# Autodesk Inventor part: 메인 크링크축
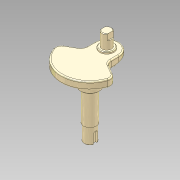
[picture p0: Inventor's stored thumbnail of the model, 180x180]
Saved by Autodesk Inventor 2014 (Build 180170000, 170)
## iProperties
Manager: KYOUNG IL JANG
Company: 한국ATC센터
Created: 2012-10
Part Number: 메인 크링크축
Document SubType Name: Modeling
Density: 1 g/cm^3
Checked By: KYOUNG IL JANG
Vendor: CBT Solutions
Designer: KYOUNG IL JANG
Material: 일반
Appearance: _시험_금속-티타늄(광택)
크링크폭: 19.000 mm
크랭크길이: 18.000 mm
크랭키위치: 65.000 mm
무게추: 90.000 mm
크랭크각도높이: 21.000 mm
크링크각도: -15.00 deg
Author: KYOUNG IL JANG
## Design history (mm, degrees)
sketch "스케치1"
  geometry: L1 (-19, 109.368)-(-19, 91.368); L2 (-19, 91.368)-(-44.545, 76.619); L3 (19, 109.368)-(19, 91.368); L4 (19, 91.368)-(44.545, 76.619); C1 r 32.5 at (0, 83) reference; C2 r 10 at (0, 83); C3 r 17.5 at (0, 83); A1 r 45 centre (0, 83) between (-44.545, 76.619) and (44.545, 76.619); A2 r 32.5 centre (0, 83) between (-19, 109.368) and (19, 109.368); A3 r 19 centre (0, 109.368) between (19, 109.368) and (-19, 109.368); 1 further point
  constraints: 8 end point, 6 point on circle, 5 centre point, 4 coincident, 2 equal length, 2 vertical alignment, 1 horizontal alignment, 1 parallel, 1 tangent, 1 vertical, 3 other
  dimensions: "d0" = 20 diameter of C2; "d1" = 35 diameter of C3; "d4" = 120 deg angle of L3 L4
  node "참조1"
extrude "돌출1" new body sketch "스케치1" distance "d7" = 12; taper "d8" = 0 deg
extrude "돌출2" join sketch "스케치1" distance "d9" = 5; taper "d10" = 0 deg
extrude "돌출3" join sketch "스케치1" distance "d11" = 100; taper "d12" = 0 deg
sketch "스케치2"
  geometry: C1 r 7.5 at (0, 109.368); C2 r 11 at (0, 109.368); A1 r 19 centre (0, 109.368) between (19, 109.368) and (-19, 109.368) reference; 1 further point
  constraints: 2 centre point, 2 coincident
  dimensions: "d13" = 15 diameter of C1; "d14" = 22 diameter of C2
extrude "돌출4" join sketch "스케치2" distance "d15" = 3; taper "d16" = 0 deg
extrude "돌출5" join sketch "스케치2" distance "d17" = 25; taper "d18" = 0 deg
node "작업 평면1"
sketch "스케치3"
  geometry: L1 (-5.75, 4.815)-(-5.75, -4.815); L2 (5.75, 4.815)-(5.75, -4.815); A1 r 7.5 centre (0, 0) between (-5.75, 4.815) and (-5.75, -4.815) reference; 1 further point
  constraints: 4 end point, 4 point on circle, 2 parallel, 1 vertical
  dimensions: "d20" = 11.5 distance between parallel lines of L2 L1
extrude "돌출6" cut sketch "스케치3" stored distance "d21" = 10; taper "d22" = 0 deg
sketch "스케치4"
  geometry: L1 (-19, 91.368)-(-19, 109.368) reference; L2 (19, 109.368)-(19, 91.368) reference; C1 r 17.5 at (0, 83) reference; 3 further points
  constraints: 2 point on line, 1 horizontal alignment, 1 other
node "작업 평면2"
  node "작업축1"
sketch "스케치5"
  geometry: L1 (0, 0)-(38, 0); L2 (38, 0)-(38, 50); L3 (38, 50)-(0, 50); L4 (0, 50)-(0, 0); L5 (38, 5.185)-(38, -12.202) reference; 2 further points
  constraints: 8 end point, 1 coincident, 1 collinear, 1 horizontal, 1 perpendicular
  dimensions: "d27" = 50 distance between parallel lines of L3 L1
extrude "돌출7" cut sketch "스케치5" stored distance "d28" = 10; taper "d29" = 0 deg
fillet "모깎기1" dims "d23" = 10, "d24" = 2
sketch "스케치6"
  geometry: C1 r 17.5 at (0, 0) reference; C2 r 15 at (0, 0); 1 further point
  constraints: 1 centre point, 1 coincident
  dimensions: "d30" = 30 diameter of C2
extrude "돌출8" join sketch "스케치6" distance "d31" = 21; taper "d32" = 0 deg
sketch "스케치7"
  geometry: C1 r 10 at (0, 0) reference; C2 r 9 at (0, 0); 1 further point
  constraints: 1 centre point, 1 coincident
  dimensions: "d33" = 1 radial gap between concentric circles of C1 C2
extrude "돌출9" cut sketch "스케치7" distance "d34" = 25; taper "d35" = 0 deg
node "작업 평면3"
sketch "스케치8"
  geometry: L1 (-9, 0)-(9, 0) reference; L2 (-3, 0)-(-3, 15); L3 (3, 15)-(3, 0); A1 r 3 centre (0, 15) between (3, 15) and (-3, 15); 2 further points
  constraints: 4 end point, 2 perpendicular, 2 point on circle, 2 point on line, 2 tangent, 1 centre point, 1 midpoint, 1 vertical alignment
  dimensions: "d36" = 6 distance between parallel lines of L3 L2; "d37" = 18 dimension on A1 L1
extrude "돌출10" cut sketch "스케치8" distance "d38" = 3.5; taper "d39" = 0 deg
chamfer "모따기1" distance "d40" = 1; stored, may be unused: second distance "d41" = 2, angle "d42" = 45 deg
node "솔리드1"
node "투영된 루프1"
other parameters: "d19" = 13
